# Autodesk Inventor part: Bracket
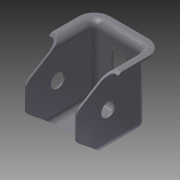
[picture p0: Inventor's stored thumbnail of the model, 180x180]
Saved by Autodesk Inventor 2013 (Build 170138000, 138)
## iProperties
Created: 2004-07
Part Number: Bracket
Document SubType Name: Modeling
Designer: leeha
Manufacturer: Standard
Standards Organization: Custom
Material: Steel, High Strength Low Alloy
Density: 7.84 g/cm^3
Mass: 269.818 g
Surface Area: 358.652 cm^2
Volume: 34.4156 cm^3
Author: Autodesk, Inc.
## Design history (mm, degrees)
sketch "Sketch1"
  geometry: L1 (-15.647, 19.059)-(44.353, 19.059); L2 (44.353, 19.059)-(44.353, -60.941); L3 (44.353, -60.941)-(-15.647, -60.941); L4 (-15.647, -60.941)-(-15.647, 19.059)
  constraints: 8 end point, 2 parallel, 1 horizontal, 1 perpendicular
  dimensions: "d0" = 60 distance of L1.start L1.end; "d1" = 80 distance of L3.end L1.start
extrude "Extrusion1" new body sketch "Sketch1" distance "d2" = 80; taper "d3" = 0 deg
shell "Shell1" dims "Shell_Thickness" = 2
fillet "Fillet1" dims "d5" = 6
fillet "Fillet2" dims "d6" = 8 (= d5 + Shell_Thickness)
sketch "Sketch2"
  geometry: L1 (-15.647, -60.941)-(-15.647, 11.059) reference; L2 (-13.647, -60.941)-(-13.647, 11.059) reference; L3 (-7.647, 17.059)-(36.353, 17.059) reference; L4 (42.353, 11.059)-(42.353, -60.941) reference; L5 (44.353, 11.059)-(44.353, -60.941) reference; L6 (-7.647, 19.059)-(36.353, 19.059) reference; L7 (54.353, -60.941)-(54.353, 11.059); L8 (36.353, 29.059)-(-7.647, 29.059); L9 (-25.647, 11.059)-(-25.647, -60.941); L10 (42.353, -60.941)-(54.353, -60.941); L11 (-13.647, -60.941)-(-25.647, -60.941); A1 r 6 centre (-7.647, 11.059) between (-7.647, 17.059) and (-13.647, 11.059) reference; A2 r 6 centre (36.353, 11.059) between (42.353, 11.059) and (36.353, 17.059) reference; A3 r 18 centre (-7.647, 11.059) between (-7.647, 29.059) and (-25.647, 11.059); A4 r 18 centre (36.353, 11.059) between (54.353, 11.059) and (36.353, 29.059)
  constraints: 10 end point, 4 point on circle, 4 tangent, 2 centre point, 2 perpendicular, 1 equal radius, 1 parallel
  dimensions: "d7" = 18 radius of A3 (= d6 + d8); "d8" = 10 distance between parallel lines of L8 L6; "d9" = 10 distance between parallel lines of L9 L1 (= d8); "d10" = 10 distance between parallel lines of L7 L5 (= d8)
extrude "Extrusion2" join sketch "Sketch2" distance "d11" = 2 (= Shell_Thickness); taper "d12" = 0 deg
fillet "Fillet3" dims "d13" = 6 (= d5)
fillet "Fillet4" dims "d14" = 8 (= d6)
sketch "Sketch3"
  geometry: L1 (-64, 0)-(-64, 72) reference; L2 (0, 0)-(-64, 0) reference; C1 r 8 at (-32, 36)
  constraints: 1 centre point
  dimensions: "d15" = 32 distance from line of C1.centre L1; "d16" = 16 diameter of C1; "d17" = 36 distance from line of L2 C1.centre
extrude "Extrusion3" cut sketch "Sketch3" taper "d19" = 0 deg; stored distance "d36" = 2 (= Shell_Thickness)
sketch "Sketch4"
  geometry: L1 (0, 0)-(-64, 0) reference; L2 (-64, 72)-(0, 72) reference; L3 (-97, 82)-(-47.383, 0.344); L4 (-17.955, -1.567)-(33, 62); L5 (33, 62)-(33, -24); L6 (33, -24)-(-97, -24); L7 (-97, -24)-(-97, 82); C1 r 8 at (-32, 36) reference; A1 r 18 centre (-32, 9.691) between (-47.383, 0.344) and (-17.955, -1.567); 1 further point
  constraints: 10 end point, 3 perpendicular, 2 point on circle, 2 tangent, 2 vertical alignment, 1 centre point, 1 midpoint
  dimensions: "d20" = 18 radius of A1; "d21" = 24 distance between parallel lines of L6 L1; "d22" = 86 distance of L4.end L5.end; "d23" = 106 distance of L6.end L3.start; "d24" = 70 deg angle of L4 L3; "d25" = 130 distance of L5.end L6.end
extrude "Extrusion4" cut sketch "Sketch4" stored distance "d26" = 2 (= Shell_Thickness); taper "d27" = 0 deg
fillet "Fillet5" dims "d28" = 8
sketch "Sketch5"
  geometry: L1 (44, 0)-(44, -64) reference; L2 (0, 0)-(44, 0) reference; L3 (0, -64)-(0, 0) reference; L4 (14, -14)-(14, -50); L5 (30, -14)-(30, -50); A1 r 8 centre (22, -14) between (30, -14) and (14, -14); A2 r 8 centre (22, -50) between (14, -50) and (30, -50); 3 further points
  constraints: 6 point on circle, 4 end point, 3 midpoint, 3 tangent, 2 centre point, 2 parallel, 2 point on line, 1 equal radius, 1 horizontal alignment, 1 vertical alignment
  dimensions: "d29" = 8 radius of A1; "d30" = 36 distance of A2.centre A1.centre
extrude "Extrusion5" cut sketch "Sketch5" stored distance "d31" = 2 (= Shell_Thickness); taper "d32" = 0 deg
sketch "Sketch6"
  geometry: L1 (0, 0)-(0, 64) reference; C1 r 14 at (22, 32); A1 r 8 centre (22, 50) between (30, 50) and (14, 50) reference; 1 further point
  constraints: 1 centre point, 1 horizontal alignment, 1 midpoint, 1 vertical alignment
  dimensions: "d33" = 28 diameter of C1
split "Split1" sketch "Sketch6"
node "Load Point (100 N)"
body "Solid1"
workplane "Work Plane1"
workaxis "Work Axis1"
